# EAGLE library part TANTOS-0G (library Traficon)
CT (03/03/2008): renamed segments of the component
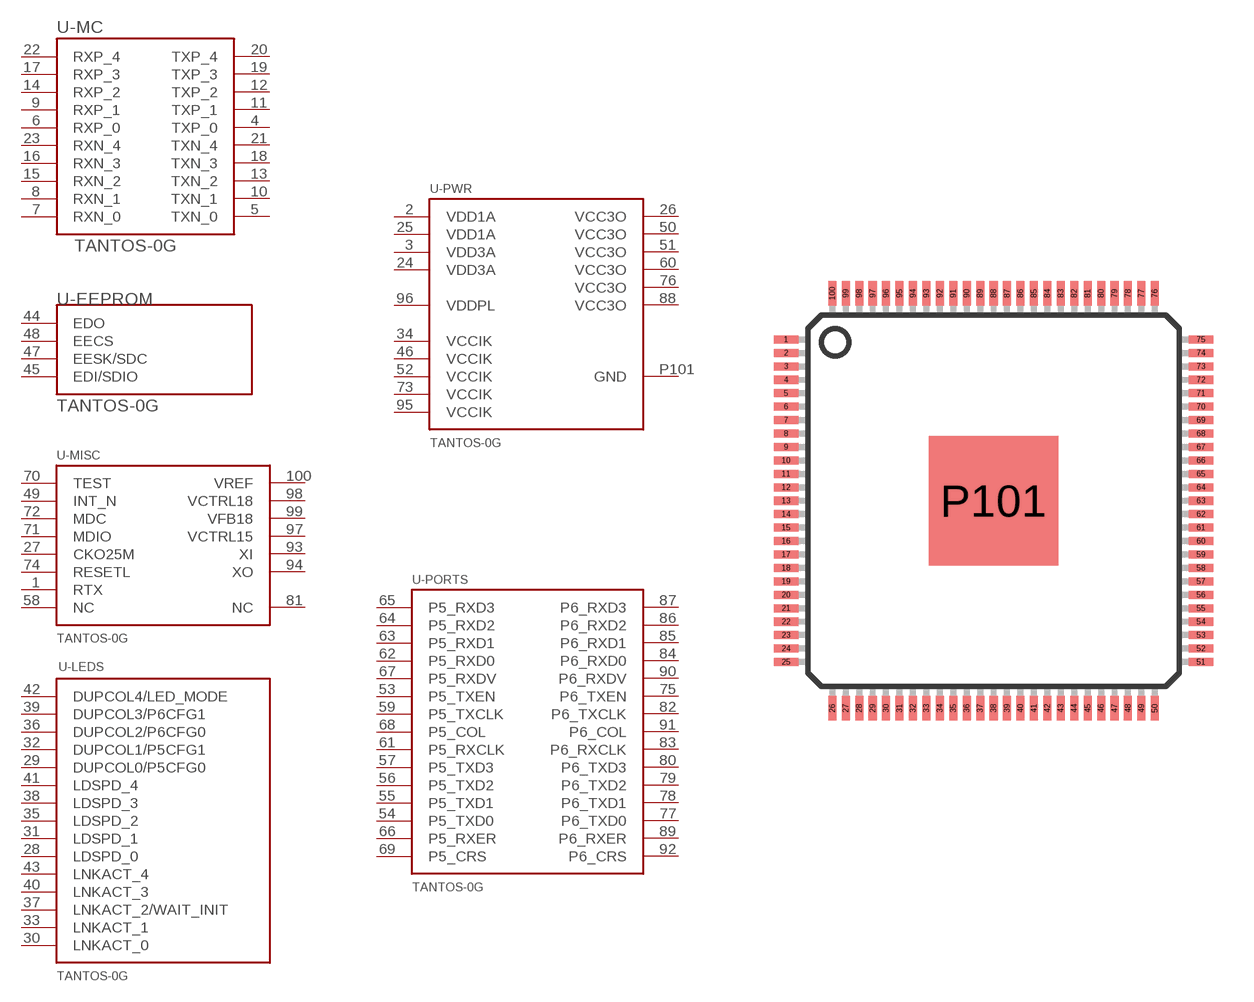
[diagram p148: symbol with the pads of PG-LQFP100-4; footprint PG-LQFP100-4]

Designator prefix U; gates -EEPROM=TANTOS-0G-EEPROM -MISC=TANTOS-0G-MISC -PORTS=TANTOS-0G-MII-PORTS -MC=TANTOS-0G-MC -LEDS=TANTOS-0G-LEDS -PWR=TANTOS-0G-PWR

## TANTOS-0G  [PG-LQFP100-4]
1  -MISC:RTX  in
2  -PWR:VDD1A  pwr
3  -PWR:VDD3A  pwr
4  -MC:TXP_0
5  -MC:TXN_0
6  -MC:RXP_0
7  -MC:RXN_0
8  -MC:RXN_1
9  -MC:RXP_1
10  -MC:TXN_1
11  -MC:TXP_1
12  -MC:TXP_2
13  -MC:TXN_2
14  -MC:RXP_2
15  -MC:RXN_2
16  -MC:RXN_3
17  -MC:RXP_3
18  -MC:TXN_3
19  -MC:TXP_3
20  -MC:TXP_4
21  -MC:TXN_4
22  -MC:RXP_4
23  -MC:RXN_4
24  -PWR:VDD3A  pwr
25  -PWR:VDD1A  pwr
26  -PWR:VCC3O  pwr
27  -MISC:CKO25M  out
28  -LEDS:LDSPD_0  out
29  -LEDS:DUPCOL0/P5CFG0
30  -LEDS:LNKACT_0  out
31  -LEDS:LDSPD_1  out
32  -LEDS:DUPCOL1/P5CFG1
33  -LEDS:LNKACT_1  out
34  -PWR:VCCIK  pwr
35  -LEDS:LDSPD_2  out
36  -LEDS:DUPCOL2/P6CFG0
37  -LEDS:LNKACT_2/WAIT_INIT  out
38  -LEDS:LDSPD_3  out
39  -LEDS:DUPCOL3/P6CFG1
40  -LEDS:LNKACT_3  out
41  -LEDS:LDSPD_4  out
42  -LEDS:DUPCOL4/LED_MODE
43  -LEDS:LNKACT_4  out
44  -EEPROM:EDO  in
45  -EEPROM:EDI/SDIO
46  -PWR:VCCIK  pwr
47  -EEPROM:EESK/SDC
48  -EEPROM:EECS  out
49  -MISC:INT_N  out
50  -PWR:VCC3O  pwr
51  -PWR:VCC3O  pwr
52  -PWR:VCCIK  pwr
53  -PORTS:P5_TXEN  out
54  -PORTS:P5_TXD0  out
55  -PORTS:P5_TXD1  out
56  -PORTS:P5_TXD2  out
57  -PORTS:P5_TXD3  out
58  -MISC:NC  nc
59  -PORTS:P5_TXCLK  in
60  -PWR:VCC3O  pwr
61  -PORTS:P5_RXCLK  in
62  -PORTS:P5_RXD0  in
63  -PORTS:P5_RXD1  in
64  -PORTS:P5_RXD2  in
65  -PORTS:P5_RXD3  in
66  -PORTS:P5_RXER  in
67  -PORTS:P5_RXDV  in
68  -PORTS:P5_COL  in
69  -PORTS:P5_CRS  in
70  -MISC:TEST  in
71  -MISC:MDIO
72  -MISC:MDC  out
73  -PWR:VCCIK  pwr
74  -MISC:RESETL  in
75  -PORTS:P6_TXEN  out
76  -PWR:VCC3O  pwr
77  -PORTS:P6_TXD0  out
78  -PORTS:P6_TXD1  out
79  -PORTS:P6_TXD2  out
80  -PORTS:P6_TXD3  out
81  -MISC:NC  nc
82  -PORTS:P6_TXCLK  in
83  -PORTS:P6_RXCLK  in
84  -PORTS:P6_RXD0  in
85  -PORTS:P6_RXD1  in
86  -PORTS:P6_RXD2  in
87  -PORTS:P6_RXD3  in
88  -PWR:VCC3O  pwr
89  -PORTS:P6_RXER  in
90  -PORTS:P6_RXDV  in
91  -PORTS:P6_COL  in
92  -PORTS:P6_CRS  in
93  -MISC:XI  in
94  -MISC:XO  out
95  -PWR:VCCIK  pwr
96  -PWR:VDDPL  pwr
97  -MISC:VCTRL15
98  -MISC:VCTRL18
99  -MISC:VFB18
100  -MISC:VREF  in
P101  -PWR:GND  pwr

## Footprint PG-LQFP100-4 (pad centres in mm)
smd 0.9 x 0.3: 1 -7.72,6; 2 -7.72,5.5; 3 -7.72,5; 4 -7.72,4.5; 5 -7.72,4; 6 -7.72,3.5; 7 -7.72,3; 8 -7.72,2.5; 9 -7.72,2; 10 -7.72,1.5; 11 -7.72,1; 12 -7.72,0.5; 13 -7.72,0; 14 -7.72,-0.5; 15 -7.72,-1; 16 -7.72,-1.5; 17 -7.72,-2; 18 -7.72,-2.5; 19 -7.72,-3; 20 -7.72,-3.5; 21 -7.72,-4; 22 -7.72,-4.5; 23 -7.72,-5; 24 -7.72,-5.5; 25 -7.72,-6; 51 7.72,-6; 52 7.72,-5.5; 53 7.72,-5; 54 7.72,-4.5; 55 7.72,-4; 56 7.72,-3.5; 57 7.72,-3; 58 7.72,-2.5; 59 7.72,-2; 60 7.72,-1.5; 61 7.72,-1; 62 7.72,-0.5; 63 7.72,0; 64 7.72,0.5; 65 7.72,1; 66 7.72,1.5; 67 7.72,2; 68 7.72,2.5; 69 7.72,3; 70 7.72,3.5; 71 7.72,4; 72 7.72,4.5; 73 7.72,5; 74 7.72,5.5; 75 7.72,6
smd 0.3 x 0.9: 26 -6,-7.72; 27 -5.5,-7.72; 28 -5,-7.72; 29 -4.5,-7.72; 30 -4,-7.72; 31 -3.5,-7.72; 32 -3,-7.72; 33 -2.5,-7.72; 34 -2,-7.72; 35 -1.5,-7.72; 36 -1,-7.72; 37 -0.5,-7.72; 38 0,-7.72; 39 0.5,-7.72; 40 1,-7.72; 41 1.5,-7.72; 42 2,-7.72; 43 2.5,-7.72; 44 3,-7.72; 45 3.5,-7.72; 46 4,-7.72; 47 4.5,-7.72; 48 5,-7.72; 49 5.5,-7.72; 50 6,-7.72; 76 6,7.72; 77 5.5,7.72; 78 5,7.72; 79 4.5,7.72; 80 4,7.72; 81 3.5,7.72; 82 3,7.72; 83 2.5,7.72; 84 2,7.72; 85 1.5,7.72; 86 1,7.72; 87 0.5,7.72; 88 0,7.72; 89 -0.5,7.72; 90 -1,7.72; 91 -1.5,7.72; 92 -2,7.72; 93 -2.5,7.72; 94 -3,7.72; 95 -3.5,7.72; 96 -4,7.72; 97 -4.5,7.72; 98 -5,7.72; 99 -5.5,7.72; 100 -6,7.72
smd 4.8 x 4.8: P101 0,0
